// Mitsubishi GX Works2 project: 3.单按钮控制(简化版)   PLC: FX3U/FX3UC

PROGRAM MAIN
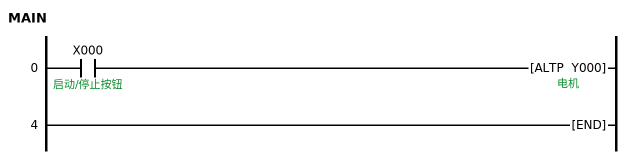
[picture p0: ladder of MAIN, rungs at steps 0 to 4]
0     LD      X000  ; 启动/停止按钮
      ALTP    Y000  ; 电机
4     END
END_PROGRAM
